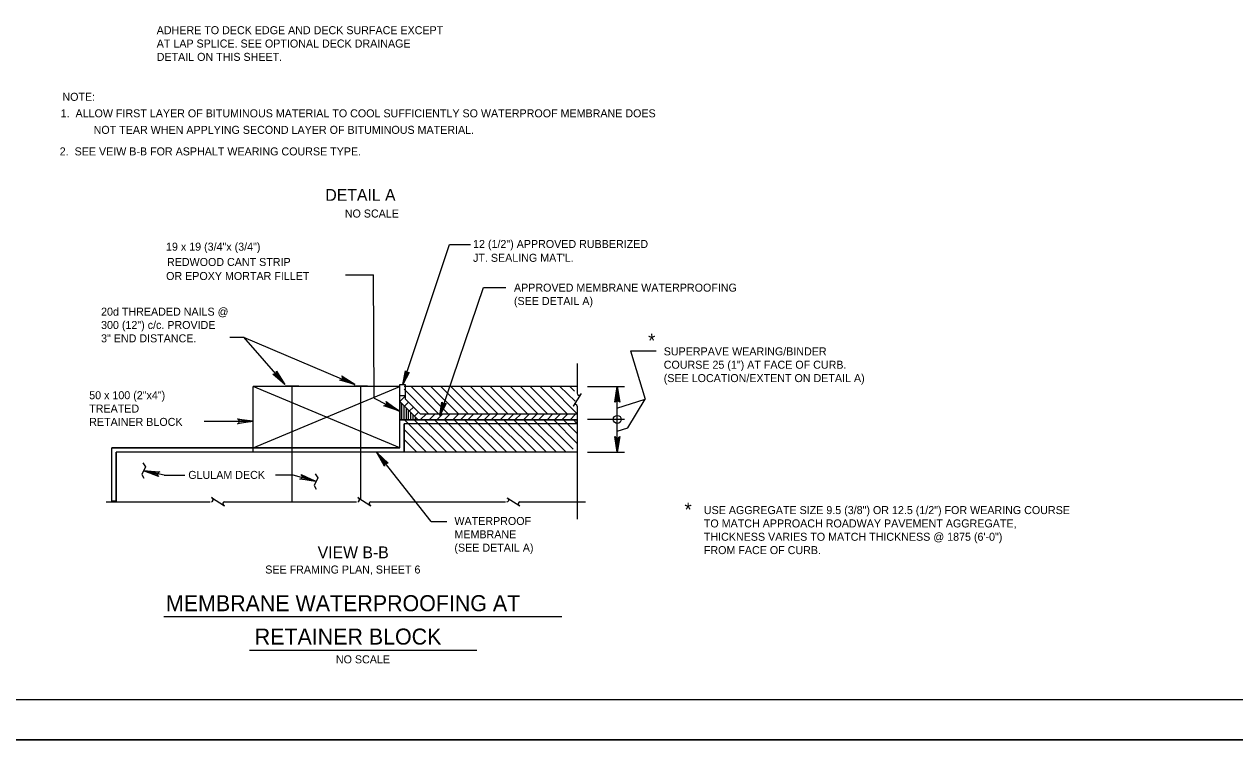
# Model space of a CAD drawing. Extents: x 638268 to 640277, y 295465 to 298435.
# Drawn here: x 638496 to 638949.9, y 296052 to 296327.6 of the extents above; entities that cross this region are included whole.
import ezdxf

# ---------------------------------------------------------------- set-up
doc = ezdxf.new("R2010")
doc.units = 0
for name, color, linetype in [('1', 7, 'Continuous'), ('2', 7, 'Continuous'), ('4', 7, 'Continuous'), ('62', 7, 'Continuous'), ('PLT-BNDY', 7, 'Continuous')]:
    doc.layers.add(name, color=color, linetype=linetype)

msp = doc.modelspace()

# ---------------------------------------------------------------- linework, layer by layer
at = {"layer": '1'}
for p, q in [((638578.15, 296210.3), (638593.71, 296192.66)), ((638578.15, 296210.3), (638619.95, 296192.66)), ((638723.33, 296205.26), (638732.97, 296205.26)), ((638723.33, 296205.26), (638728.84, 296187.07)), ((638581.79, 296168.84), (638636.8, 296191.81)), ((638636.8, 296168.84), (638581.79, 296191.81)), ((638593.84, 296192.1), (638598.98, 296192.1)), ((638596.41, 296148.68), (638596.41, 296192.1)), ((638619.61, 296192.1), (638624.75, 296192.1)), ((638622.18, 296149.63), (638622.18, 296192.1)), ((638718.17, 296183.74), (638728.84, 296187.07)), ((638722.33, 296176.41), (638728.84, 296187.07)), ((638721.05, 296179.43), (638707.19, 296179.43)), ((638718.35, 296175.17), (638722.33, 296176.41))]:
    msp.add_line(p, q, dxfattribs=at)
for points in [[(638717.65, 296186.28), (638718.05, 296186.48), (638718.35, 296191.81), (638717.65, 296186.28), (638717.41, 296185.99), (638718.35, 296191.81), (638718.61, 296186.49), (638719.01, 296186.29), (638718.35, 296191.81), (638719.27, 296185.99), (638719.01, 296186.29)], [(638576.26, 296179.52), (638576.46, 296179.12), (638581.79, 296178.82), (638576.26, 296179.52), (638575.97, 296179.76), (638581.79, 296178.82), (638576.47, 296178.56), (638576.27, 296178.16), (638581.79, 296178.82), (638575.97, 296177.9), (638576.27, 296178.16)], [(638719.04, 296172.78), (638718.64, 296172.57), (638718.35, 296167.24), (638719.04, 296172.78), (638719.28, 296173.06), (638718.35, 296167.24), (638718.08, 296172.57), (638717.69, 296172.76), (638718.35, 296167.24), (638717.42, 296173.06), (638717.69, 296172.76)]]:
    msp.add_lwpolyline(points, dxfattribs=at)
msp.add_circle((638718.35, 296179.52), 1.5, dxfattribs=at)
at = {"layer": '2'}
for p, q in [((638637.9, 296192.6), (638655.5, 296245.02)), ((638655.5, 296245.02), (638663.37, 296245.02)), ((638616.46, 296233.66), (638626.97, 296233.66)), ((638627.18, 296187.5), (638626.97, 296233.66)), ((638652.01, 296181.52), (638668.14, 296228.97)), ((638668.14, 296228.97), (638676.58, 296228.97)), ((638573.07, 296210.3), (638578.15, 296210.3)), ((638703.34, 296200.47), (638703.34, 296189.3)), ((638636.8, 296191.81), (638581.79, 296191.81)), ((638581.79, 296167.24), (638581.79, 296191.81)), ((638636.8, 296191.81), (638629.39, 296191.81)), ((638636.8, 296186.33), (638636.8, 296191.81)), ((638703.34, 296191.81), (638638.4, 296191.81)), ((638702.71, 296191.81), (638639.53, 296191.81)), ((638641.09, 296191.81), (638651.38, 296181.52)), ((638644.79, 296191.81), (638655.09, 296181.52)), ((638648.5, 296191.81), (638658.88, 296181.52)), ((638652.2, 296191.81), (638662.59, 296181.52)), ((638655.91, 296191.81), (638666.29, 296181.52)), ((638659.61, 296191.81), (638670, 296181.52)), ((638663.32, 296191.81), (638673.7, 296181.52)), ((638667.02, 296191.81), (638677.41, 296181.52)), ((638670.73, 296191.81), (638681.11, 296181.52)), ((638674.43, 296191.81), (638684.82, 296181.52)), ((638678.33, 296191.81), (638688.63, 296181.52)), ((638682.04, 296191.81), (638692.33, 296181.52)), ((638685.74, 296191.81), (638696.04, 296181.52)), ((638689.45, 296191.81), (638699.74, 296181.52)), ((638693.15, 296191.81), (638703.1, 296181.87)), ((638696.86, 296191.81), (638702.51, 296186.35)), ((638700.56, 296191.81), (638702.32, 296190.06)), ((638707.19, 296191.81), (638721.05, 296191.81)), ((638718.35, 296179.53), (638718.35, 296191.81)), ((638627.18, 296187.5), (638636.43, 296182.76)), ((638636.77, 296186.29), (638638.9, 296188.42)), ((638638.4, 296190.8), (638647.68, 296181.52)), ((638638.9, 296187.13), (638638.9, 296188.51)), ((638638.9, 296187.13), (638644.51, 296181.52)), ((638636.79, 296179.42), (638636.79, 296186.26)), ((638636.79, 296186.26), (638643.64, 296179.42)), ((638636.8, 296179.73), (638636.8, 296186.17)), ((638638.55, 296184.5), (638640.04, 296185.99)), ((638640.45, 296182.69), (638641.89, 296184.14)), ((638703.34, 296184.44), (638703.34, 296142.09)), ((638563.46, 296178.82), (638581.79, 296178.82)), ((638643.64, 296179.42), (638636.8, 296179.42)), ((638636.8, 296168.84), (638636.8, 296179.42)), ((638638.61, 296179.42), (638650.78, 296167.24)), ((638642.22, 296179.42), (638654.4, 296167.24)), ((638642.32, 296180.73), (638643.81, 296182.22)), ((638703.22, 296179.42), (638643.64, 296179.42)), ((638703.22, 296181.52), (638644.51, 296181.52)), ((638644.61, 296179.45), (638646.68, 296181.52)), ((638646.07, 296179.42), (638658.25, 296167.24)), ((638647.87, 296179.42), (638649.97, 296181.52)), ((638649.83, 296179.36), (638661.95, 296167.24)), ((638650.7, 296179.38), (638652.84, 296181.52)), ((638653.51, 296179.39), (638665.66, 296167.24)), ((638653.53, 296179.46), (638655.59, 296181.52)), ((638656.75, 296179.42), (638658.85, 296181.52)), ((638657.09, 296179.51), (638669.36, 296167.24)), ((638659.58, 296179.38), (638661.72, 296181.52)), ((638661.08, 296179.34), (638673.28, 296167.24)), ((638662.41, 296179.46), (638664.47, 296181.52)), ((638664.74, 296179.39), (638676.99, 296167.24)), ((638665.59, 296179.42), (638667.69, 296181.52)), ((638668.42, 296179.38), (638670.56, 296181.52)), ((638668.46, 296179.37), (638680.69, 296167.24)), ((638671.24, 296179.46), (638673.31, 296181.52)), ((638672.14, 296179.4), (638684.4, 296167.24)), ((638674.43, 296179.42), (638676.53, 296181.52)), ((638675.85, 296179.38), (638688.1, 296167.24)), ((638677.25, 296179.38), (638679.39, 296181.52)), ((638679.49, 296179.45), (638691.81, 296167.24)), ((638680.08, 296179.46), (638682.14, 296181.52)), ((638683.22, 296179.42), (638685.33, 296181.52)), ((638683.29, 296179.36), (638695.51, 296167.24)), ((638686.05, 296179.38), (638688.19, 296181.52)), ((638686.95, 296179.4), (638699.22, 296167.24)), ((638688.88, 296179.46), (638690.94, 296181.52)), ((638690.75, 296179.39), (638701.84, 296168.31)), ((638692.02, 296179.42), (638694.12, 296181.52)), ((638694.39, 296179.46), (638703.34, 296170.51)), ((638694.85, 296179.38), (638696.99, 296181.52)), ((638697.68, 296179.46), (638699.74, 296181.52)), ((638698.17, 296179.38), (638703.34, 296174.22)), ((638700.63, 296179.42), (638702.73, 296181.52)), ((638701.83, 296179.43), (638703.35, 296177.91)), ((638718.35, 296167.24), (638718.35, 296179.53)), ((638703.22, 296177.82), (638638.4, 296177.82)), ((638638.4, 296167.24), (638638.4, 296177.82)), ((638638.4, 296175.7), (638646.86, 296167.24)), ((638638.4, 296172.01), (638643.16, 296167.24)), ((638636.8, 296168.84), (638528.83, 296168.84)), ((638528.83, 296148.9), (638528.83, 296168.84)), ((638703.34, 296167.24), (638530.43, 296167.24)), ((638530.43, 296148.9), (638530.43, 296167.24)), ((638636.8, 296167.24), (638581.79, 296167.24)), ((638707.19, 296167.24), (638721.05, 296167.24)), ((638548.46, 296158.6), (638556.22, 296158.6)), ((638590.16, 296158.79), (638596.69, 296158.79)), ((638526.68, 296148.68), (638565.7, 296148.68)), ((638571.11, 296148.68), (638620.57, 296148.68)), ((638626.02, 296148.61), (638676.46, 296148.61)), ((638681.8, 296148.61), (638706.48, 296148.61)), ((638648.57, 296141.28), (638654.41, 296141.28)), ((638548.36, 296105.65), (638697.57, 296105.65)), ((638580.4, 296093.09), (638665.7, 296093.09)), ((639261.46, 296074.46), (638475.46, 296074.46))]:
    msp.add_line(p, q, dxfattribs=at)
for points in [[(638640.1, 296197.06), (638639.55, 296196.98), (638637.9, 296192.6), (638640.1, 296197.06), (638640.37, 296197.09), (638637.9, 296192.6), (638639.13, 296197.07), (638638.94, 296197.46), (638637.9, 296192.6), (638638.9, 296197.73), (638638.94, 296197.46)], [(638704.66, 296188.94), (638704.85, 296189.24), (638701.83, 296184.43), (638702.03, 296184.75)], [(638653.96, 296185.43), (638653.57, 296185.23), (638651.81, 296180.94), (638653.96, 296185.43), (638654.15, 296185.43), (638651.81, 296180.94), (638652.98, 296185.43), (638652.79, 296185.62), (638651.81, 296180.94), (638652.59, 296186.01), (638652.79, 296185.62)], [(638566.54, 296150.01), (638566.24, 296150.2), (638571.05, 296147.17), (638570.73, 296147.38)], [(638621.41, 296150.01), (638621.11, 296150.2), (638625.92, 296147.17), (638625.6, 296147.38)], [(638677.3, 296149.94), (638677, 296150.12), (638681.81, 296147.1), (638681.49, 296147.3)]]:
    msp.add_lwpolyline(points, dxfattribs=at)
for centre, start, end in [((638704.05, 296189.3), 180, 330), ((638702.63, 296184.38), 5.3286, 147.8672), ((638566.18, 296149.4), 270, 60), ((638571.11, 296147.98), 95.3286, 237.8672), ((638621.05, 296149.4), 270, 60), ((638625.98, 296147.98), 95.3286, 237.8672), ((638676.94, 296149.32), 270, 60), ((638681.86, 296147.9), 95.3286, 237.8672)]:
    msp.add_arc(centre, 0.71, start, end, dxfattribs=at)
at = {"layer": '62'}
for p, q in [((638637.59, 296179.42), (638637.59, 296185.47)), ((638638.43, 296179.42), (638638.43, 296184.63)), ((638639.27, 296179.42), (638639.27, 296183.79)), ((638640.11, 296179.42), (638640.11, 296182.95)), ((638640.95, 296179.42), (638640.95, 296182.11)), ((638641.79, 296179.42), (638641.79, 296181.27)), ((638642.64, 296179.42), (638642.64, 296180.41)), ((638648.57, 296141.28), (638628.16, 296167.09)), ((638548.46, 296158.6), (638540.88, 296160.24)), ((638596.69, 296158.79), (638605.21, 296156.36))]:
    msp.add_line(p, q, dxfattribs=at)
for points in [[(638590.58, 296197.28), (638590.41, 296196.86), (638593.71, 296192.66), (638590.58, 296197.28), (638590.57, 296197.65), (638593.71, 296192.66), (638590, 296196.49), (638589.57, 296196.38), (638593.71, 296192.66), (638589.17, 296196.43), (638589.57, 296196.38)], [(638615.19, 296195.57), (638615.21, 296195.12), (638619.95, 296192.66), (638615.19, 296195.57), (638615.03, 296195.91), (638619.95, 296192.66), (638614.99, 296194.61), (638614.65, 296194.33), (638619.95, 296192.66), (638614.26, 296194.21), (638614.65, 296194.33)], [(638631.82, 296185.9), (638631.82, 296185.45), (638636.43, 296182.76), (638631.82, 296185.9), (638631.68, 296186.25), (638636.43, 296182.76), (638631.57, 296184.95), (638631.21, 296184.69), (638636.43, 296182.76), (638630.83, 296184.59), (638631.21, 296184.69)], [(638631.05, 296162.31), (638631.24, 296162.73), (638628.16, 296167.09), (638631.05, 296162.31), (638631.04, 296161.94), (638628.16, 296167.09), (638631.67, 296163.07), (638632.1, 296163.17), (638628.16, 296167.09), (638632.5, 296163.1), (638632.1, 296163.17)], [(638540.39, 296163.26), (638541.46, 296161.8), (638540.1, 296158.88), (638540.88, 296157.52)], [(638546.14, 296158.39), (638546.02, 296158.83), (638540.88, 296160.24), (638546.14, 296158.39), (638546.37, 296158.09), (638540.88, 296160.24), (638546.14, 296159.37), (638546.41, 296159.72), (638540.88, 296160.24), (638546.76, 296159.91), (638546.41, 296159.72)], [(638600.08, 296158.55), (638600.16, 296158.11), (638605.21, 296156.36), (638600.08, 296158.55), (638599.87, 296158.86), (638605.21, 296156.36), (638600.02, 296157.57), (638599.72, 296157.24), (638605.21, 296156.36), (638599.36, 296157.07), (638599.72, 296157.24)], [(638605.01, 296159.08), (638606.08, 296157.62), (638604.72, 296154.7), (638605.5, 296153.34)]]:
    msp.add_lwpolyline(points, dxfattribs=at)
for points in [[(638636.73, 296188.51), (638638.9, 296188.51), (638638.9, 296192.54), (638636.73, 296192.54)], [(638636.79, 296186.26), (638636.79, 296179.42), (638643.64, 296179.42)], [(638703.22, 296179.42), (638703.22, 296177.82), (638638.4, 296177.82), (638638.4, 296167.24), (638530.43, 296167.24), (638530.43, 296148.9), (638528.83, 296148.9), (638528.83, 296168.84), (638636.8, 296168.84), (638636.79, 296179.42)]]:
    msp.add_lwpolyline(points, close=True, dxfattribs=at)
at = {"layer": 'PLT-BNDY'}
for points in [[(638435.46, 296653.46), (639276.46, 296653.46), (639276.46, 296059.46), (638435.46, 296059.46)], [(638435.46, 296059.46), (639276.46, 296059.46), (639276.46, 295465.46), (638435.46, 295465.46)]]:
    msp.add_lwpolyline(points, close=True, dxfattribs=at)

# ---------------------------------------------------------------- texts
at = {"layer": '1'}
for p in [(638729.91, 296206.46), (638743.56, 296143.14)]:
    msp.add_text('*', height=5.18, dxfattribs=at).set_placement(p)
at = {"layer": '2'}
for s, height, p in [('12 (1/2") APPROVED RUBBERIZED', 3, (638664.27, 296243.77)), ('19 x 19 (3/4"x (3/4")', 3, (638549.14, 296242.76)), ("JT. SEALING MAT'L.", 3, (638664.27, 296238.59)), ('REDWOOD CANT STRIP', 3, (638549.51, 296237.03)), ('OR EPOXY MORTAR FILLET', 3, (638549.18, 296231.77)), ('APPROVED MEMBRANE WATERPROOFING', 3, (638679.61, 296227.41)), ('(SEE DETAIL A)', 3, (638679.61, 296222.41)), ('20d THREADED NAILS @', 3, (638524.79, 296218.41)), ('300 (12") c/c. PROVIDE', 3, (638524.79, 296213.41)), ('3" END DISTANCE.', 3, (638524.79, 296208.41)), ('SUPERPAVE WEARING/BINDER', 3, (638735.77, 296203.52)), ('COURSE 25 (1") AT FACE OF CURB.', 3, (638735.77, 296198.52)), ('(SEE LOCATION/EXTENT ON DETAIL A)', 3, (638735.77, 296193.51)), ('50 x 100 (2"x4") ', 3, (638520.34, 296187.09)), ('TREATED', 3, (638520.34, 296182.09)), ('RETAINER BLOCK', 3, (638520.34, 296177.09)), ('GLULAM DECK', 3, (638557.49, 296157.22)), ('USE AGGREGATE SIZE 9.5 (3/8") OR 12.5 (1/2") FOR WEARING COURSE', 3, (638750.82, 296144.04)), ('WATERPROOF', 3, (638657.29, 296139.96)), ('TO MATCH APPROACH ROADWAY PAVEMENT AGGREGATE,', 3, (638750.82, 296139.04)), ('MEMBRANE', 3, (638657.29, 296134.96)), ('THICKNESS VARIES TO MATCH THICKNESS @ 1875 (6\'-0")', 3, (638750.82, 296134.04)), ('(SEE DETAIL A)', 3, (638657.29, 296129.96)), ('FROM FACE OF CURB.', 3, (638750.82, 296129.04)), ('MEMBRANE WATERPROOFING AT', 6, (638549.12, 296107.64)), ('RETAINER BLOCK', 6, (638582.4, 296095.13))]:
    msp.add_text(s, height=height, dxfattribs=at).set_placement(p)
at = {"layer": '4'}
for s, height, p in [('ADHERE TO DECK EDGE AND DECK SURFACE EXCEPT', 3, (638545.65, 296323.9)), ('AT LAP SPLICE. SEE OPTIONAL DECK DRAINAGE ', 3, (638545.65, 296318.9)), ('DETAIL ON THIS SHEET.', 3, (638545.65, 296313.9)), ('NOTE:', 3, (638510.29, 296298.93)), ('1.  ALLOW FIRST LAYER OF BITUMINOUS MATERIAL TO COOL SUFFICIENTLY SO WATERPROOF MEMBRANE DOES ', 3, (638509.63, 296292.74)), ('NOT TEAR WHEN APPLYING SECOND LAYER OF BITUMINOUS MATERIAL.', 3, (638522, 296286.55)), ('2.  SEE VEIW B-B FOR ASPHALT WEARING COURSE TYPE.', 3, (638509.28, 296278.47)), ('DETAIL A', 4.429, (638608.88, 296261.45)), ('NO SCALE', 3, (638616.18, 296255.19)), ('VIEW B-B', 4.429, (638606, 296127.49)), ('SEE FRAMING PLAN, SHEET 6', 3, (638586.35, 296121.76)), ('NO SCALE', 3, (638612.84, 296088.09))]:
    msp.add_text(s, height=height, dxfattribs=at).set_placement(p)

doc.saveas('drawing.dxf')
